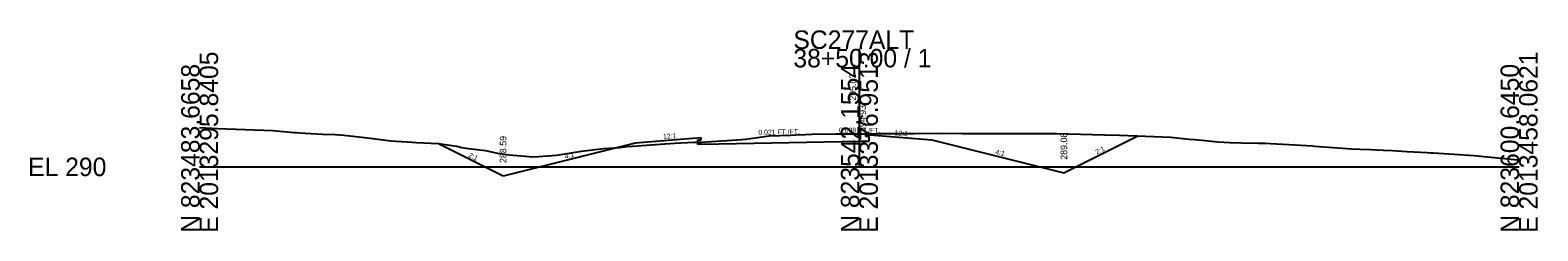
# Model space of a CAD drawing. Extents: x 205929 to 2357175, y -1785700 to 827636.
# Drawn here: x 2018394.5 to 2018623, y 826534.6 to 826565 of the extents above; entities that cross this region are included whole.
import ezdxf

# ---------------------------------------------------------------- set-up
doc = ezdxf.new("R2010")
doc.units = 0
for name, color, linetype in [('RD_GPK_XS_Cell', 7, 'Continuous'), ('RD_XS_Base', 7, 'Continuous'), ('RD_XS_EarthShd', 7, 'Continuous'), ('RD_XS_ExGround', 7, 'Continuous'), ('RD_XS_Pave', 7, 'Continuous'), ('RD_XS_TieSlope', 7, 'Continuous'), ('RD_XS_TX_Elev_EX', 7, 'Continuous'), ('RD_XS_TX_Elev_PR', 7, 'Continuous'), ('RD_XS_TX_ShdSlope', 7, 'Continuous'), ('RD_XS_TX_Slope', 7, 'Continuous')]:
    doc.layers.add(name, color=color, linetype=linetype)

msp = doc.modelspace()

# ---------------------------------------------------------------- linework, layer by layer
at = {"layer": 'RD_GPK_XS_Cell'}
for p, q in [((2018520.17, 826544.26), (2018520.17, 826562.14)), ((2018420.17, 826544.26), (2018520.17, 826544.26)), ((2018520.17, 826544.26), (2018620.17, 826544.26))]:
    msp.add_line(p, q, dxfattribs=at)
at = {"layer": 'RD_XS_Base'}
for p, q in [((2018496.17, 826547.68), (2018520.17, 826548.18)), ((2018520.17, 826548.18), (2018521.17, 826548.17))]:
    msp.add_line(p, q, dxfattribs=at)
at = {"layer": 'RD_XS_EarthShd'}
for p, q in [((2018496.17, 826548.68), (2018486.17, 826547.85)), ((2018521.17, 826549.17), (2018531.17, 826548.34))]:
    msp.add_line(p, q, dxfattribs=at)
at = {"layer": 'RD_XS_ExGround'}
msp.add_lwpolyline([(2018420.17, 826550.22), (2018422.94, 826550.07), (2018431.26, 826549.79), (2018434.52, 826549.47), (2018434.85, 826549.45), (2018435.29, 826549.42), (2018438.79, 826549.24), (2018440.69, 826549.16), (2018442.01, 826549.05), (2018443.84, 826548.88), (2018445.59, 826548.66), (2018446.85, 826548.5), (2018449.17, 826548.22), (2018452.39, 826548), (2018453.02, 826547.95), (2018456.34, 826547.8), (2018459.18, 826547.38), (2018459.92, 826547.21), (2018460.94, 826547.04), (2018463.5, 826546.73), (2018465.34, 826546.34), (2018467.08, 826546.08), (2018469.49, 826545.88), (2018470.66, 826545.78), (2018471.51, 826545.81), (2018474.24, 826546.06), (2018478.04, 826546.64), (2018481.41, 826547.02), (2018483.84, 826547.19), (2018484.99, 826547.33), (2018486.58, 826547.44), (2018488.57, 826547.59), (2018490, 826547.69), (2018492.15, 826547.85), (2018495.13, 826547.99), (2018495.73, 826548.01), (2018496.17, 826548.03), (2018499.32, 826548.2), (2018502.33, 826548.43), (2018502.9, 826548.47), (2018503.68, 826548.58), (2018506.48, 826548.96), (2018509.73, 826549.08), (2018510.56, 826549.11), (2018512, 826549.18), (2018512.95, 826549.21), (2018516.61, 826549.25), (2018520.17, 826549.29), (2018520.94, 826549.29), (2018522.69, 826549.3), (2018524.63, 826549.31), (2018528.55, 826549.33), (2018532.07, 826549.35), (2018535.81, 826549.34), (2018539.69, 826549.33), (2018544.99, 826549.32), (2018550.04, 826549.32), (2018557.35, 826549.13), (2018559.59, 826549.07), (2018560.93, 826549.01), (2018567.37, 826548.76), (2018570.14, 826548.48), (2018570.95, 826548.4), (2018572.07, 826548.3), (2018574.53, 826548.06), (2018576.3, 826547.97), (2018578.11, 826547.91), (2018580.62, 826547.87), (2018581.69, 826547.86), (2018582.47, 826547.82), (2018585.28, 826547.63), (2018588.86, 826547.44), (2018589.17, 826547.42), (2018594.8, 826547), (2018596.02, 826546.93), (2018597.72, 826546.87), (2018599.6, 826546.78), (2018600.96, 826546.72), (2018603.18, 826546.61), (2018606.26, 826546.43), (2018606.77, 826546.4), (2018607.13, 826546.38), (2018610.35, 826546.18), (2018613.29, 826545.96), (2018613.93, 826545.91), (2018614.81, 826545.84), (2018617.51, 826545.59), (2018619.46, 826545.37), (2018620.17, 826545.28)], dxfattribs=at)
at = {"layer": 'RD_XS_Pave'}
for p, q in [((2018495.67, 826548.34), (2018496.17, 826548.35)), ((2018495.67, 826547.67), (2018495.67, 826548.34)), ((2018496.17, 826547.68), (2018495.67, 826547.67)), ((2018496.17, 826548.35), (2018496.17, 826548.68)), ((2018521.17, 826548.84), (2018521.17, 826549.17)), ((2018521.67, 826548.84), (2018521.17, 826548.84)), ((2018521.17, 826548.17), (2018521.67, 826548.17)), ((2018521.67, 826548.17), (2018521.67, 826548.84))]:
    msp.add_line(p, q, dxfattribs=at)
at = {"layer": 'RD_XS_TieSlope'}
for p, q in [((2018466.17, 826542.85), (2018456.27, 826547.8)), ((2018486.17, 826547.85), (2018466.17, 826542.85)), ((2018531.17, 826548.34), (2018551.17, 826543.34)), ((2018551.17, 826543.34), (2018562.4, 826548.96))]:
    msp.add_line(p, q, dxfattribs=at)

# ---------------------------------------------------------------- texts
at = {"layer": 'RD_GPK_XS_Cell'}
for s, p in [('SC277ALT', (2018510.17, 826562.14)), ('38+50.00 / 1', (2018510.17, 826559.34)), ('EL 290', (2018394.17, 826542.86))]:
    msp.add_text(s, height=2.8, dxfattribs=at).set_placement(p)
for s, p in [('E 2013295.8405', (2018422.97, 826534.26)), ('E 2013376.9513', (2018522.97, 826534.26)), ('E 2013458.0621', (2018622.97, 826534.26)), ('N 823483.6658', (2018420.17, 826534.26)), ('N 823542.1554', (2018520.17, 826534.26)), ('N 823600.6450', (2018620.17, 826534.26))]:
    msp.add_text(s, height=2.8, rotation=90, dxfattribs=at).set_placement(p)
at = {"layer": 'RD_XS_TX_Elev_EX'}
msp.add_text('295.03', height=1, rotation=90, dxfattribs=at).set_placement((2018519.67, 826554.29))
at = {"layer": 'RD_XS_TX_Elev_PR'}
for s, p in [(' 294.93', (2018521.17, 826549.18)), ('288.59', (2018466.67, 826544.85)), ('289.08', (2018551.67, 826545.34))]:
    msp.add_text(s, height=1, rotation=90, dxfattribs=at).set_placement(p)
at = {"layer": 'RD_XS_TX_ShdSlope'}
for rotation, p in [(4.7636, (2018490.44, 826548.46)), (355.2364, (2018525.48, 826549.07))]:
    msp.add_text('12:1', height=0.75, rotation=rotation, dxfattribs=at).set_placement(p)
at = {"layer": 'RD_XS_TX_Slope'}
for s, rotation, p in [('0.021 FT./FT.', 1.1916, (2018504.88, 826549.11)), ('0.008 FT./FT.', 359.5619, (2018517.08, 826549.46)), ('2:1', 333.4349, (2018460.83, 826545.8)), ('4:1', 14.0362, (2018475.6, 826545.46)), ('4:1', 345.9638, (2018540.72, 826546.21)), ('2:1', 26.5651, (2018556.17, 826546.12))]:
    msp.add_text(s, height=0.75, rotation=rotation, dxfattribs=at).set_placement(p)

doc.saveas('drawing.dxf')
